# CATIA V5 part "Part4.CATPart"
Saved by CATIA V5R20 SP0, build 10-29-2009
Part number: Part4
Bounding box of the stored display mesh (mm): x -400 to 150, y -79.813 to 429.814, z -80 to 80
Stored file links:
  E:\新建文件夹 (2)\Part4.CATPart
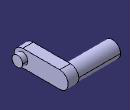
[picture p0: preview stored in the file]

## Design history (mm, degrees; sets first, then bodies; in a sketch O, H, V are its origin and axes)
Body1 (main body)
  Sketch1 on yz-plane, origin (0, 0, 0), H (0, 1, 0), V (0, 0, 1)
    arc A1 centre (0, 0) radius 80 from (0, 80) to (0, -80) ccw
    point P1 (0, 80)
    arc A2 centre (350, 0) radius 80 from (350, -80) to (350, 80) ccw
    line L1 (0, 80) -> (350, 80)
    line L2 (0, -80) -> (350, -80)
    point P3 (0, -80)
    coincidence: P1 V, P3 V
    tangency: L1 A1, L2 A2
  Pad1: profile Sketch1, direction (1, 0, 0), length 100
  Sketch2 on end face of Pad1, origin (100, 0, 0), H (0, 1, 0), V (0, 0, 1)
    circle A1 centre (0, 0) radius 50
  Pad2: profile Sketch2, direction (1, 0, 0), length 50
  Sketch3 on start face of Pad1, origin (0, 0, 0), H (0, -1, 0), V (0, 0, 1)
    circle A1 centre (-350, 0) radius 75
    point P1 (-350, 0)
    coincidence: P1 H
  Pad3: profile Sketch3, direction (-1, 0, 0), length 400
